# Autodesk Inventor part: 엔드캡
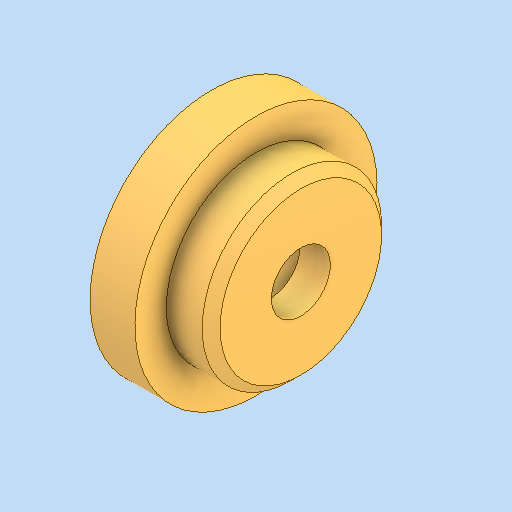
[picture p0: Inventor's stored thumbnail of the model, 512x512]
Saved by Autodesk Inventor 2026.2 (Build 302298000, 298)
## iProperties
Created: 2026-01
Part Number: 엔드캡
Material: 강철, 연강
Document SubType Name: Modeling
Designer: PC2-07
Density: 7.85 g/cm^3
Appearance: 기본값
Author: jhkim
Sending System: Autodesk Inventor 2026
Preprocessor: ST-DEVELOPER v20.1
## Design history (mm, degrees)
feature "솔리드1"
node "솔리드2"
